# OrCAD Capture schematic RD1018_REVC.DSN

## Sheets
1 PAGE2: size B
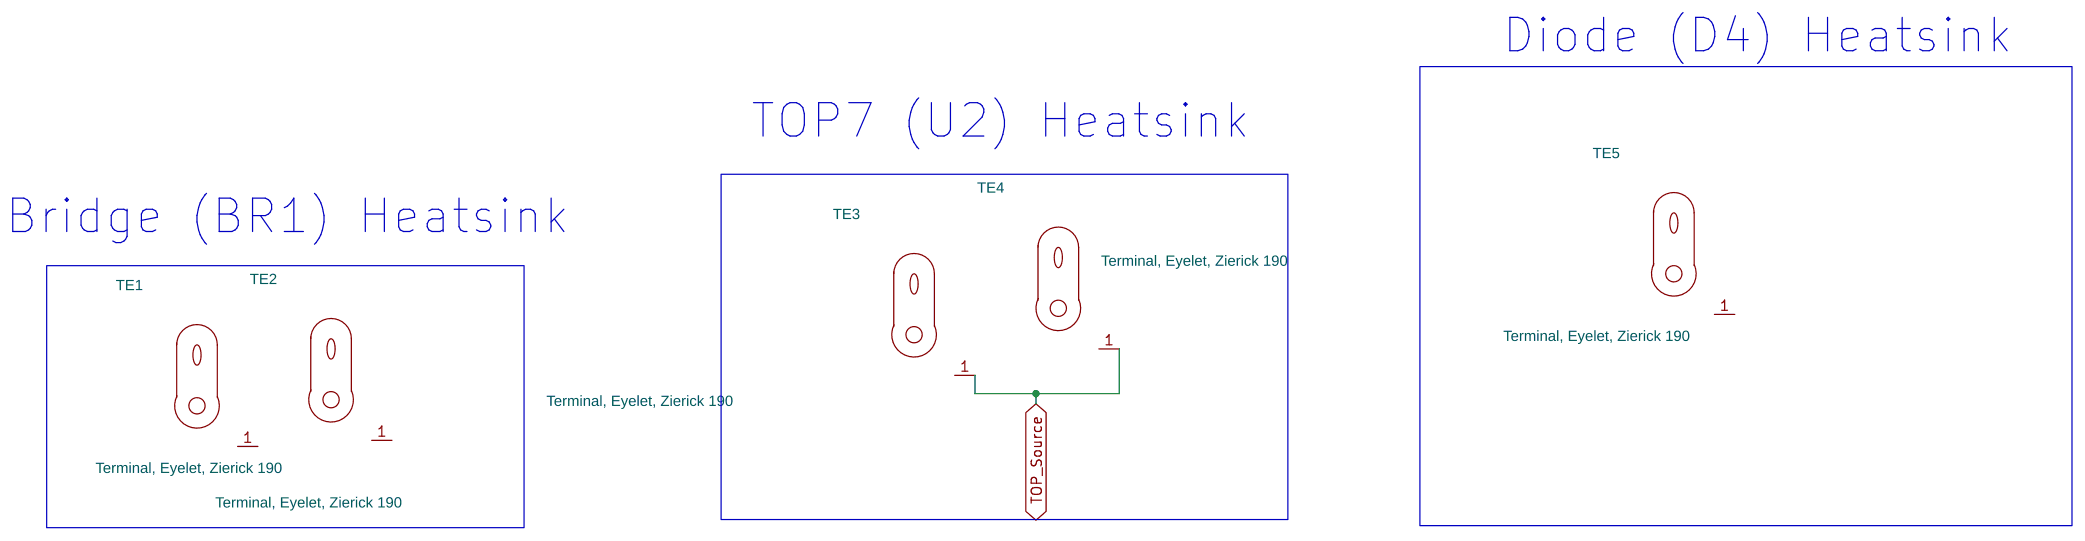
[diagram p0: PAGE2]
2 PAGE1: size Custom
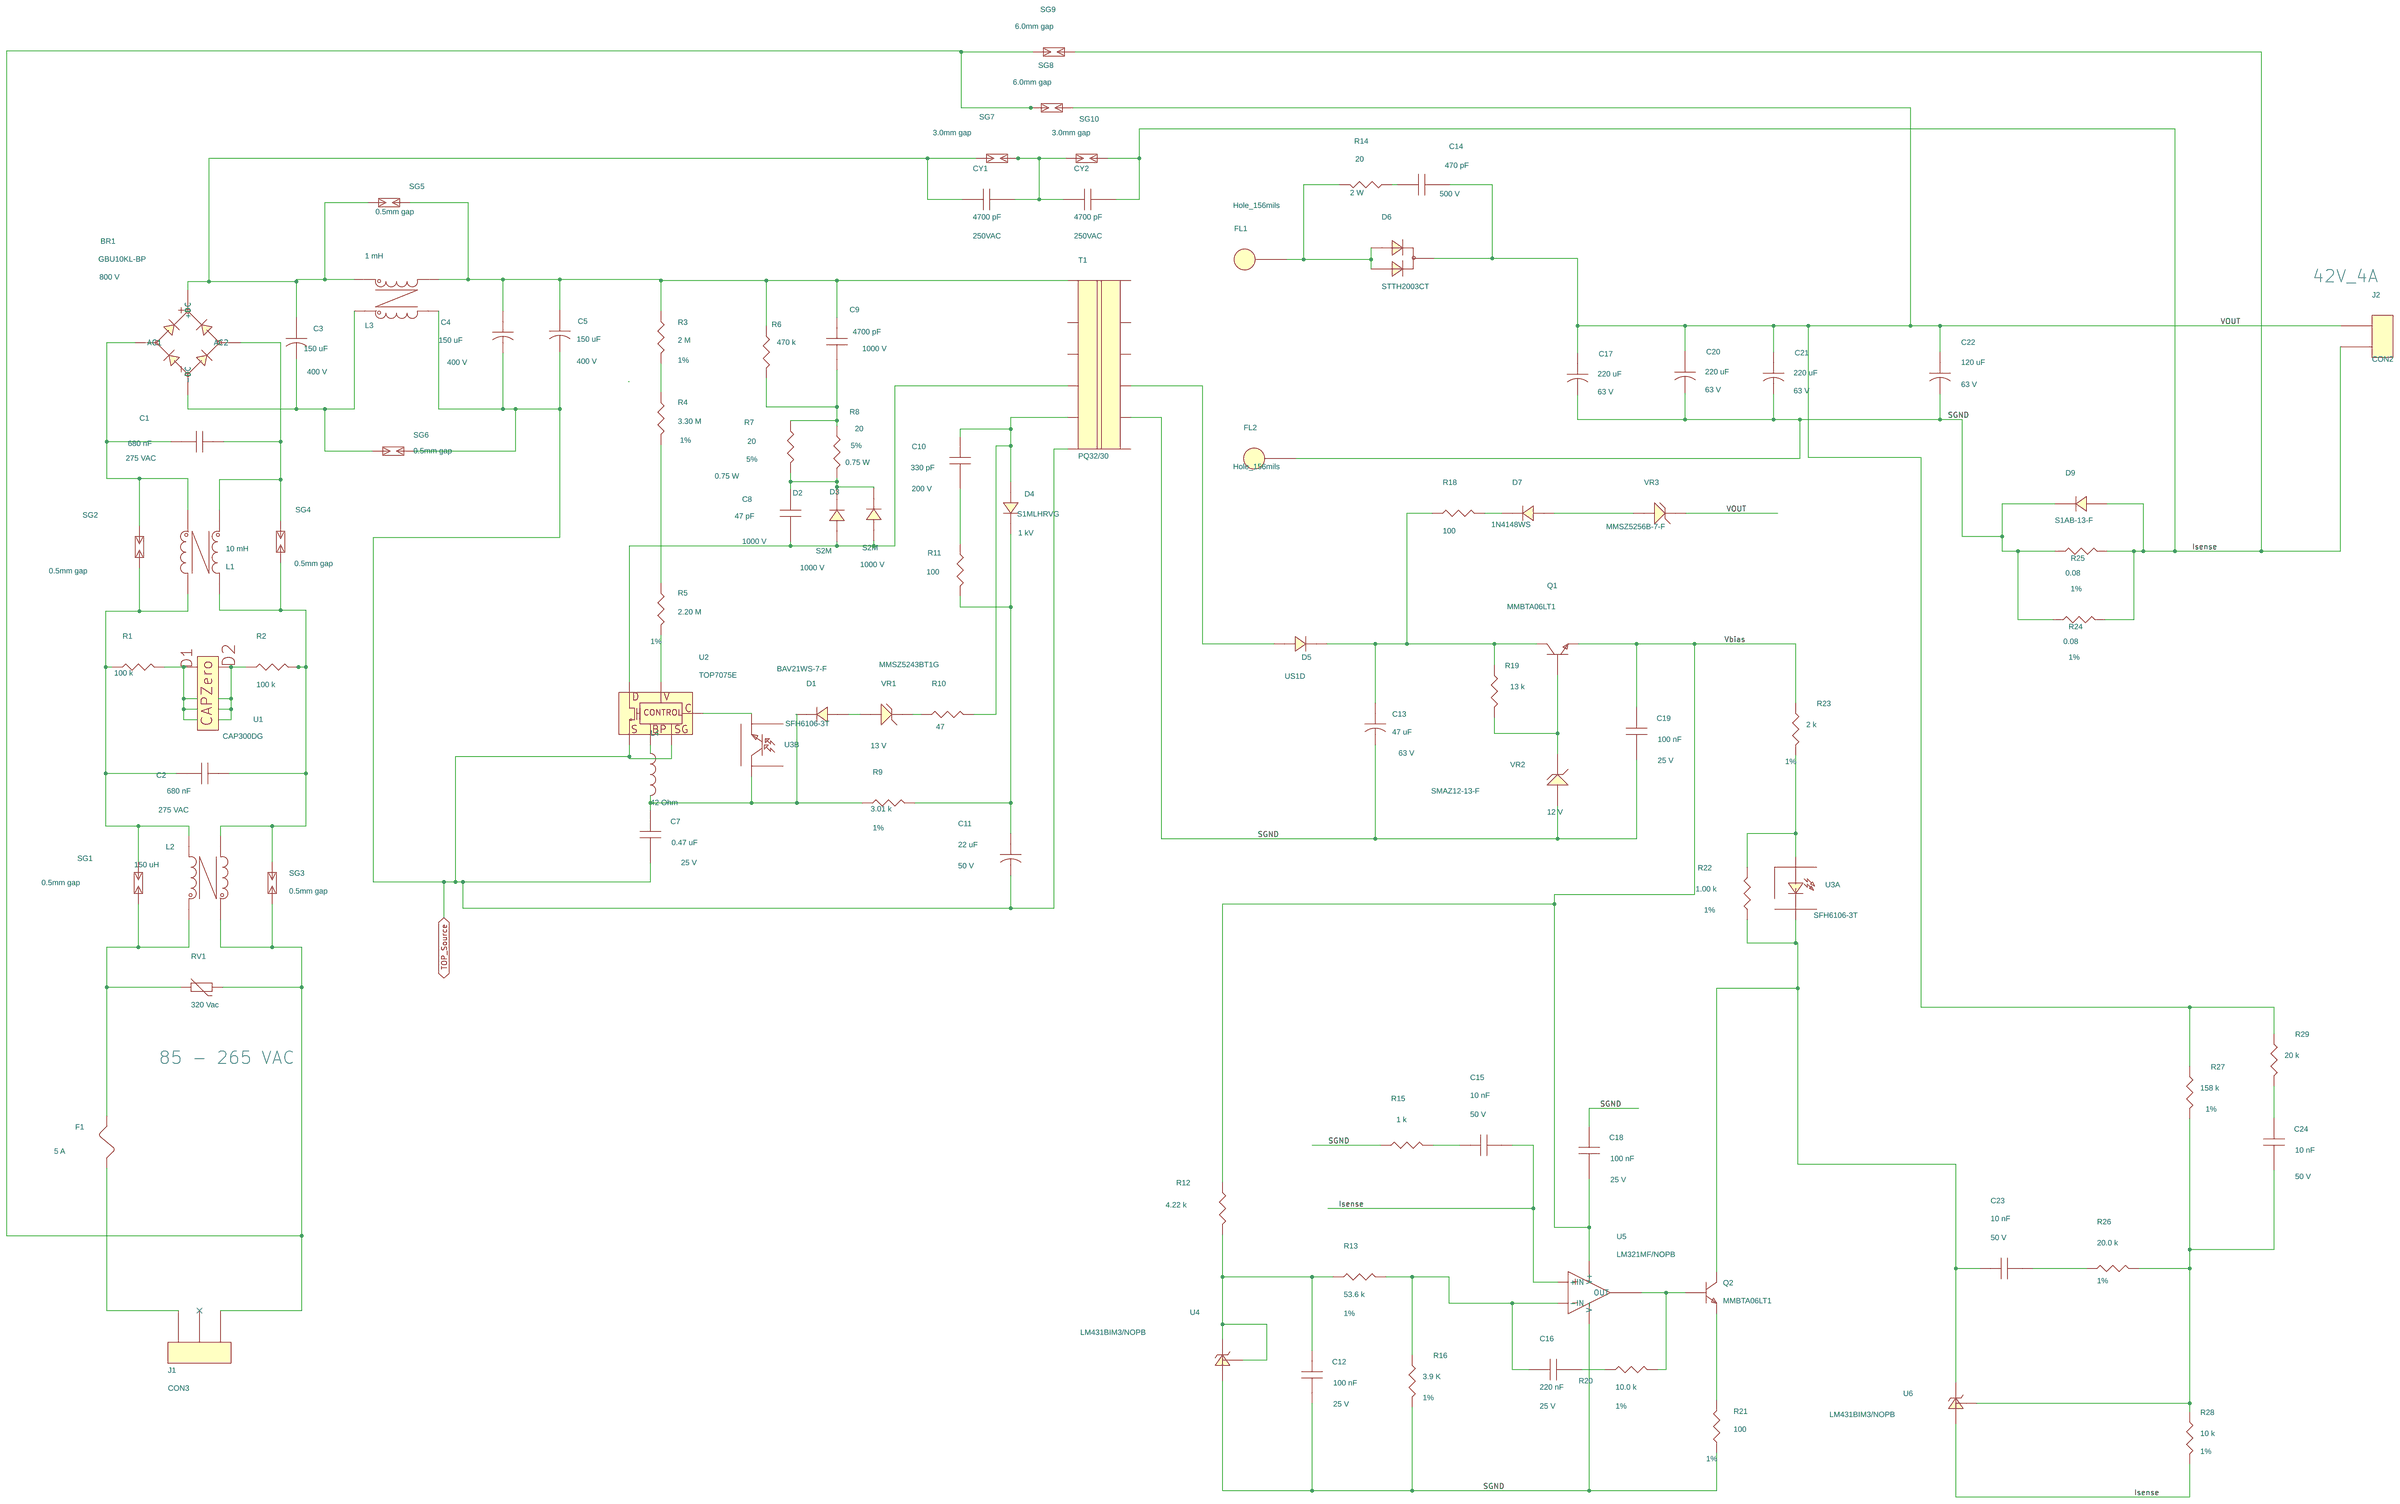
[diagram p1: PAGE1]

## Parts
sheet PAGE1
BR1  GBU10KL-BP  [pidaxbridgegbu8]
C1  680 nF  [pinpxcaprad710x430720040]
C2  680 nF  [pinpxcaprad710x430720040]
C3  150 uF  [pipolcapclyd18ls7p5H37d40V]
C4  150 uF  [pipolcapclyd18ls7p5H37d40V]
C5  150 uF  [pipolcapclyd18ls7p5H37d40V]
C7  0.47 uF  [pismc0805]
C8  47 pF  [pismc0805]
C9  4700 pF  [pismc1206]
C10  330 pF  [pismc0805]
C11  22 uF  [pipolcapcyld250ls100030]
C12  100 nF  [pismc0805]
C13  47 uF  [pipolcapcyld250ls100030]
C14  470 pF  [pismc0805]
C15  10 nF  [pismc0805]
C16  220 nF  [pismc0603]
C17  220 uF  [pipolcapclyd10mm040]
C18  100 nF  [pismc0805]
C19  100 nF  [pismc0805]
C20  220 uF  [pipolcapclyd10mm040]
C21  220 uF  [pipolcapclyd10mm040]
C22  120 uF  [pipolcapclyd10mm040]
C23  10 nF  [pismc0805]
C24  10 nF  [pismc0805]
CY1  4700 pF  [pinpcaprad10dx7p5mm]
CY2  4700 pF  [pinpcaprad10dx7p5mm]
D1  BAV21WS-7-F  [pismsod323]
D2  S2M  [pismsmb]
D3  S2M  [pismsmb]
D4  S1MLHRVG  [pi_sm_sod-123_12]
D5  US1D  [pismdsma]
D6  STTH2003CT  [pidvto2203]
D7  1N4148WS  [pismdsod323]
D9  S1AB-13-F  [pismsmb]
F1  5 A  [pi_rst_microfuse]
FL1  Hole_156mils  [pi_hole_156mil]
FL2  Hole_156mils  [pi_hole_156mil]
J1  CON3  [pi_hdr_3pin_phoenix_196ls]
J2  CON2  [pi_hdr_2pin_phoenix_196ls]
L1  10 mH  [pi_toroid_balun_1]
L2  150 uH  [pi_toroid_CMC4p_V_RDK1018]
L3  1 mH  [PI4P21P7X11P5D60]
L4  42 Ohm  [INDC2012X105N]
Q1  MMBTA06LT1  [pismsot23123_1]
Q2  MMBTA06LT1  [pismsot23123_1]
R1  100 k  [pismr1206]
R2  100 k  [pismr1206]
R3  2 M  [pismr1206]
R4  3.30 M  [pismr1206]
R5  2.20 M  [pismr1206]
R6  470 k  [pismr1206]
R7  20  [pismr2010]
R8  20  [pismr2010]
R9  3.01 k  [pismr0805]
R10  47  [pismr0603]
R11  100  [pismr0805]
R12  4.22 k  [pismr0805]
R13  53.6 k  [pismr0603]
R14  20  [pi2wresd200ls725d040]
R15  1 k  [pismr0805]
R16  3.9 K  [pismr0603]
R18  100  [pismr0805]
R19  13 k  [pismr0805]
R20  10.0 k  [pismr1206]
R21  100  [pismr0805]
R22  1.00 k  [pismr0805]
R23  2 k  [pismr1206]
R24  0.08  [pismr2010]
R25  0.08  [pismr2010]
R26  20.0 k  [pismr0805]
R27  158 k  [pismr0805]
R28  10 k  [pismr0805]
R29  20 k  [pismr0805]
RV1  320 Vac  [pidisc500x225ls335x140040]
SG1  0.5mm gap  [PI_SPARK_GAP_0p5MM]
SG2  0.5mm gap  [PI_SPARK_GAP_0p5MM]
SG3  0.5mm gap  [PI_SPARK_GAP_0p5MM]
SG4  0.5mm gap  [PI_SPARK_GAP_0p5MM]
SG5  0.5mm gap  [PI_SPARK_GAP_0p5MM]
SG6  0.5mm gap  [PI_SPARK_GAP_0p5MM]
SG7  3.0mm gap  [PI_SPARK_GAP_3p0MM]
SG8  6.0mm gap  [PI_SPARK_GAP_6p0MM]
SG9  6.0mm gap  [PI_SPARK_GAP_6p0MM]
SG10  3.0mm gap  [PI_SPARK_GAP_3p0MM]
T1  PQ32/30  [pi_bbn_TDKbpq32_30_12p]
U1  CAP300DG  [pi_ic_smd_so8_capzero]
U2  TOP7075E  [piicesip76th]
U3  SFH6106-3T  [SMD-4_VO_VIS]  (sections A,B)
U4  LM431BIM3/NOPB  [pismsot23123]
U5  LM321MF/NOPB  [pismsot235]
U6  LM431BIM3/NOPB  [pismsot23123]
VR1  MMSZ5243BT1G  [pi_sm_sod-123_12]
VR2  SMAZ12-13-F  [pismdo214ac12]
VR3  MMSZ5256B-7-F  [pi_sm_sod-123_12]
sheet PAGE2
TE1  Terminal, Eyelet, Zierick 190  [pi_zierick190_eyelet]
TE2  Terminal, Eyelet, Zierick 190  [pi_zierick190_eyelet]
TE3  Terminal, Eyelet, Zierick 190  [pi_zierick190_eyelet]
TE4  Terminal, Eyelet, Zierick 190  [pi_zierick190_eyelet]
TE5  Terminal, Eyelet, Zierick 190  [pi_zierick190_eyelet]

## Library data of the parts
BR1 = DISCRETE_BRIDGE_+~~-: Disp_Voltage: 800 V; Part Number: 15-01989-00; ROOM: 1
C1 C2 = CAP_NP: ALT_SYMBOLS: pinpxcaprad710x430720040_h; Disp_Voltage: 275 VAC; FPLIST: pinpxcaprad710x430720040,pinpxcaprad710x430720040_h; Part Number: 20-00611-00; ROOM: 1; Voltage: 275 VAC
C3-C5 = CAP_POL: ALT_SYMBOLS: pipolcapclyd18ls7p5H37d40H; Disp_Voltage: 400 V; FPLIST: pipolcapclyd18ls7p5H37d40V,pipolcapclyd18ls7p5H37d40H; Part Number: 20-00860-00; ROOM: 1; Voltage: 400 V
C7 = CAP_NP: ALT_SYMBOLS: Unisem_RMCF0805UL; Disp_Voltage: 25 V; FPLIST: pismc0805,Unisem_RMCF0805UL; Part Number: 20-09182-00; ROOM: 1; Voltage: 25 V
C8 = CAP_NP: ALT_SYMBOLS: Unisem_RMCF0805UL; Disp_Voltage: 1000 V; FPLIST: pismc0805,Unisem_RMCF0805UL; Part Number: 20-01040-00; ROOM: 1; Tol: 10; Voltage: 1000 V
C9 = CAP_NP: Disp_Voltage: 1000 V; Part Number: 20-01475-00; ROOM: 1; Tol: 10; Voltage: 1000 V
C10 = CAP_NP: ALT_SYMBOLS: Unisem_RMCF0805UL; Disp_Voltage: 200 V; FPLIST: pismc0805,Unisem_RMCF0805UL; Part Number: 20-01506-00; ROOM: 1; Tol: 10; Voltage: 200 V
C11 = CAP_POL: Disp_Voltage: 50 V; Part Number: 20-00056-00; ROOM: 1; Tol: 20
C12 C18 C19 = CAP_NP: ALT_SYMBOLS: Unisem_RMCF0805UL; Disp_Voltage: 25 V; FPLIST: pismc0805,Unisem_RMCF0805UL; Part Number: 20-08599-00; Voltage: 25 V
C13 = CAP_POL: ALT_SYMBOLS: pipolcapcyld250ls100030h; Disp_Voltage: 63 V; FPLIST: pipolcapcyld250ls100030,pipolcapcyld250ls100030h; Part Number: 20-08610-00; Voltage: 63 V
C14 = CAP_NP: ALT_SYMBOLS: Unisem_RMCF0805UL; COMPGROUP: 2; Disp_Voltage: 500 V; FPLIST: pismc0805,Unisem_RMCF0805UL; Part Number: 20-09175-00; ROOM: 2; Tol: 10; Voltage: 500 V
C15 = CAP_NP: Disp_Voltage: 50 V; Part Number: 20-00965-00; Voltage: 50 V
C16 = CAP_NP: ALT_SYMBOLS: Unisem_RMCF0603UL; Disp_Voltage: 25 V; FPLIST: pismc0603,Unisem_RMCF0603UL; Part Number: 20-00530-00; Voltage: 25 V
C17 C20 C21 = CAP_POL: Disp_Voltage: 63 V; PCB Editor PCBFP: pipolcapcyld400ls200040; Part Number: 20-00981-00; ROOM: 2; Voltage: 63 V
C22 = CAP_POL: ALT_SYMBOLS: pipolcapclyd395x630ls200030h; Disp_Voltage: 63 V; FPLIST: pipolcapclyd10mm040,pipolcapclyd395x630ls200030h; PCB Editor PCBFP: pipolcapclyd320ls140030; Part Number: 20-00980-00; ROOM: 2; Tol: 20; Voltage: 63 V
C23 C24 = CAP_NP: Disp_Voltage: 50 V; Part Number: 20-09227-00; Voltage: 50 V
CY1 CY2 = CAP_NP: Disp_Voltage: 250VAC; Part Number: 20-01632-00; Voltage: 250VAC
D1 = DIODE: ALT_SYMBOLS: SOD323_UL_IPC,pismsod323_1; FPLIST: pismsod323,SOD323_UL_IPC,pismsod323_1; Part Number: 15-00385-00
D2 D3 = DIODE: Disp_Voltage: 1000 V; Part Number: 15-02112-00; ROOM: 1
D4 = DIODE: Disp_Voltage: 1 kV; Part Number: 15-01663-00; ROOM: 1
D5 = DIODE: Part Number: 15-00492-00
D6 = D_DUAL_CK_AKA: ALT_SYMBOLS: pidvto2203vf1; FPLIST: pidvto2203,pidvto2203vf1; Part Number: 15-01131-00
D7 = DIODE: Part Number: 15-01163-00; ROOM: 1
D9 = DIODE: Part Number: 15-00994-00
F1 = FUSE: ALT_SYMBOLS: pirstmicrofusehoz; COMPGROUP: 1; FPLIST: pi_rst_microfuse,pirstmicrofusehoz; Part Number: 40-00052-00; ROOM: 1
FL1 FL2 = FlyingLead: Part Number: 35-00420-00; ROOM: 2
J1 = CON3: ALT_SYMBOLS: pi_hdr_3pin_phoenix_196lsobl; FPLIST: pi_hdr_3pin_phoenix_196ls,pi_hdr_3pin_phoenix_196lsobl; Part Number: 35-00351-00
J2 = CON2: ALT_SYMBOLS: pi_hdr_2pin_phoenix_196lsobl; FPLIST: pi_hdr_2pin_phoenix_196ls,pi_hdr_2pin_phoenix_196lsobl; Part Number: 35-00153-00
L1 = TORRID_4P_12_43a: Part Number: 32-00016-00; ROOM: 1
L2 = TORRID_4P_12_43a: Part Number: 32-00486-00
L3 = TORRID_4P_14_23: ALT_SYMBOLS: pi_toroid_CMC_RDK1018_L3; FPLIST: PI4P21P7X11P5D60, pi_toroid_CMC_RDK1018_L3; Part Number: 32-00487-00
L4 = INDUCTOR_BEAD: Part Number: 30-00656-00
Q1 Q2 = NPN_BEC: Part Number: 55-00030-00
R1 R2 = R: Part Number: 05-01400-00; ROOM: 1
R3 = R: Disp_Tol: 1%; Part Number: 05-06512-00; ROOM: 1
R4 = R: Disp_Tol: 1%; Part Number: 05-05359-00; ROOM: 1
R5 = R: Disp_Tol: 1%; Part Number: 05-03157-00; ROOM: 1
R6 = R: Part Number: 05-01416-00; ROOM: 1
R7 R8 = R: Disp_Power: 0.75 W; Disp_Tol: 5%; Part Number: 05-06629-00; ROOM: 1
R9 = R: ALT_SYMBOLS: Unisem_RMCF0805UL; Disp_Tol: 1%; FPLIST: pismr0805,Unisem_RMCF0805UL; Part Number: 05-03354-00
R10 = R: ALT_SYMBOLS: Unisem_RMCF0603UL,pismr0603_1; FPLIST: pismr0603,Unisem_RMCF0603UL,pismr0603_1; Part Number: 05-01656-00
R11 = R: ALT_SYMBOLS: Unisem_RMCF0805UL; Disp_Tol: 1%; FPLIST: pismr0805,Unisem_RMCF0805UL; Part Number: 05-06641-00; ROOM: 1
R12 = R: ALT_SYMBOLS: Unisem_RMCF0805UL; Disp_Tol: 1%; FPLIST: pismr0805,Unisem_RMCF0805UL; Part Number: 05-03367-00; ROOM: 3
R13 = R: ALT_SYMBOLS: Unisem_RMCF0603UL; Disp_Tol: 1%; FPLIST: pismr0603,Unisem_RMCF0603UL; Part Number: 05-03254-00
R14 = R: ALT_SYMBOLS: pi2wresd200ls900d040,pi2wvresd200ls300d040,pi2wvresd200ls400d040; Disp_Power: 2 W; FPLIST: pi2wresd200ls725d040,pi2wresd200ls900d040,pi2wvresd200ls300d040,pi2wvresd200ls400d040; PCB Editor PCBFP: pi14wvresd100ls100d030,pi14wvresd100ls200d030,pi14wresd100ls400d030,pi14wresd100ls500d030; Part Number: 05-02963-00; ROOM: 2
R15 = R: Part Number: 05-01519-00
R16 = R: ALT_SYMBOLS: Unisem_RMCF0603UL; Disp_Tol: 1%; FPLIST: pismr0603,Unisem_RMCF0603UL; Part Number: 05-06885-00
R18 = R: ALT_SYMBOLS: Unisem_RMCF0805UL; Disp_Power: 0.25 W; Disp_Tol: 1%; FPLIST: pismr0805,Unisem_RMCF0805UL; Part Number: 05-06616-00; ROOM: 2
R19 = R: ALT_SYMBOLS: Unisem_RMCF0805UL; FPLIST: pismr0805,Unisem_RMCF0805UL; Part Number: 05-01546-00
R20 = R: Disp_Tol: 1%; Part Number: 05-00289-00
R21 = R: ALT_SYMBOLS: Unisem_RMCF0805UL; Disp_Tol: 1%; FPLIST: pismr0805,Unisem_RMCF0805UL; Part Number: 05-06641-00
R22 = R: ALT_SYMBOLS: Unisem_RMCF0805UL; Disp_Tol: 1%; FPLIST: pismr0805,Unisem_RMCF0805UL; Part Number: 05-03310-00
R23 = R: Disp_Tol: 1%; Part Number: 05-00222-00
R24 R25 = R: Disp_Power: 1 W; Disp_Tol: 1%; Part Number: 05-07888-00
R26 = R: ALT_SYMBOLS: Unisem_RMCF0805UL; Disp_Tol: 1%; FPLIST: pismr0805,Unisem_RMCF0805UL; Part Number: 05-00713-00
R27 = R: ALT_SYMBOLS: Unisem_RMCF0805UL; Disp_Tol: 1%; FPLIST: pismr0805,Unisem_RMCF0805UL; Part Number: 05-00799-00
R28 = R: ALT_SYMBOLS: Unisem_RMCF0805UL; Disp_Tol: 1%; FPLIST: pismr0805,Unisem_RMCF0805UL; GROUP: 2; Part Number: 05-00684-00
R29 = R: Part Number: 05-01550-00
RV1 = VARISTOR: ALT_SYMBOLS: pi_rad450x550ls300d040_h; FPLIST: pidisc500x225ls335x140040,pi_rad450x550ls300d040_h; Part Number: 85-00018-00; ROOM: 1
SG1-SG6 = SPARK_GAP: Part Number: 66-00529-00
SG7 SG10 = SPARK_GAP: Part Number: 66-00359-00
SG8 SG9 = SPARK_GAP: Part Number: 66-00525-00; ROOM: 1
T1 = BPQ32_30_12P_GENERIC: Part Number: 25-01198-00
U1 = CAPZero: Part Number: 10-01229-00; ROOM: 1
U2 = TOPSwitch-GaN_eSIP7: Part Number: 10-01638-00
U3 = OPTO_A_B_AKCE: Part Number: 53-00042-00
U4 = TL431_SOT-23_CAR: Part Number: 45-00232-00
U5 = LM321_SOT23-5: Part Number: 45-00049-00
U6 = TL431_SOT-23_CAR: Note: Do Not Collect; Part Number: 45-00232-00
VR1 = DIODE_ZENER: Disp_Voltage: 13 V; Part Number: 15-00710-00
VR2 = DIODE_ZENER: Disp_Voltage: 12 V; Part Number: 15-01776-00
VR3 = DIODE_ZENER: Part Number: 15-01096-00; ROOM: 2
TE1 = TERM_EYLT: Part Number: 60-00016-00; ROOM: 1
TE2-TE5 = TERM_EYLT: Part Number: 60-00016-00

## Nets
SGND: C12.2 C13.2 C17.2 C18.1 C19.2 C20.2 C21.2 C22.2 D9.1 FL2.1 R15.1 R16.2 R21.1 R24.1 R25.1 T1.8 U4.2(A) U5.2(V-) VR2.2
Isense: C15.2 CY2.2 D9.2 J2.2 R24.2 R25.2 R28.2 SG9.2 SG10.2 U5.1(+IN) U6.2(A)
TOP_Source: C4.2 C5.2 C7.2 C11.2 L3.3 SG6.2 T1.6 TE3.1 TE4.1 U2.4 U2.5
Vbias: C18.2 C19.1 Q1.2(EMITTER) R12.1 R23.1 U5.5(V+)
VOUT: C14.2 C17.1 C20.1 C21.1 C22.1 D6.2(Cathode) J2.1 R27.1 R29.1 SG8.2 VR3.1
N1180640: BR1.1(+DC) C3.1 CY1.1 L3.1 SG5.1 SG7.1
N1180998: BR1.4(-DC) C3.2 L3.2 SG6.1
N1181144: R3.2 R4.1
N1181148: C8.2 D2.2 D3.2 T1.4 U2.7
N1181266: C11.1 D4.1 R9.2 R11.2
N1181568: U2.3 U3.4(E)
N11509583: C2.2 L1.3 L2.2 R1.1 SG1.2 SG2.1
N11509663: R1.2 U1.1(NC1) U1.2(D1) U1.3(NC2) U1.4(NC3)
N11509667: R2.1 U1.5(NC4) U1.6(NC5) U1.7(D2) U1.8(NC8)
N11509713: C2.1 L1.2 L2.3 R2.2 SG3.2 SG4.1
N11509765: F1.2 L2.1 RV1.1 SG1.1
N11509809: J1.3 L2.4 RV1.2 SG3.1 SG8.1 SG9.1
N11511065: BR1.2(AC1) C1.2 L1.4 SG2.2
N11555399: C4.1 C5.1 C9.1 L3.4 R3.1 R6.1 SG5.2 T1.1
N11558446: BR1.3(AC2) C1.1 L1.1 SG4.2
N11565135: C9.2 R6.2 R7.1 R8.1
N11566250: F1.1 J1.1
N11618494: C10.1 D4.2 R10.2 T1.5
N11648004: R4.2 R5.1
N12700328: R5.2 U2.1
N12700744: C7.1 D1.1 L4.2 R9.1 U3.3(C)
N12704773: C10.2 R11.1
N12706416: C14.1 R14.1
N12706737: D6.1(A1) D6.3(A2) FL1.1 R14.2
N12714802: C13.1 D5.1 Q1.3(COLLECTOR) R18.2 R19.2
N12714870: Q1.1(BASE) R19.1 VR2.1
N12715244: R22.1 R23.2 U3.1(A)
N12715260: C24.1 R29.2
N12715348: C23.1 Q2.3(COLLECTOR) R22.2 U3.2(K) U6.1(C)
N12715398: C24.2 R26.2 R27.2 R28.1 U6.3(VREF)
N12715470: C23.2 R26.1
N12715572: C15.1 R15.2
N12715722: C12.1 R12.2 R13.1 U4.1(C) U4.3(VREF)
N12715816: C16.1 R13.2 R16.1 U5.3(-IN)
N12715884: Q2.2(EMITTER) R21.2
N12716022: Q2.1(BASE) R20.2 U5.4(OUT)
N12720334: D5.2 T1.9
N12811611: C8.1 D2.1 D3.1 R7.2 R8.2
N12855423: D1.2 VR1.2
N12855454: R10.1 VR1.1
N12858106: C16.2 R20.1
N12858350: L4.1 U2.2
N12858425: CY1.2 CY2.1 SG7.2 SG10.1
N13059333: D7.1 R18.1
N13059337: D7.2 VR3.2

Not connected (* = marked no-connect by the designer): J1 2*; T1 2 3 7 10 11 12; TE1 1; TE2 1; TE5 1

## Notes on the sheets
sheet 1
- Diode (D4) Heatsink
- TOP7 (U2) Heatsink
- Bridge (BR1) Heatsink
sheet 2
- 42V_4A
- 85 - 265 VAC
